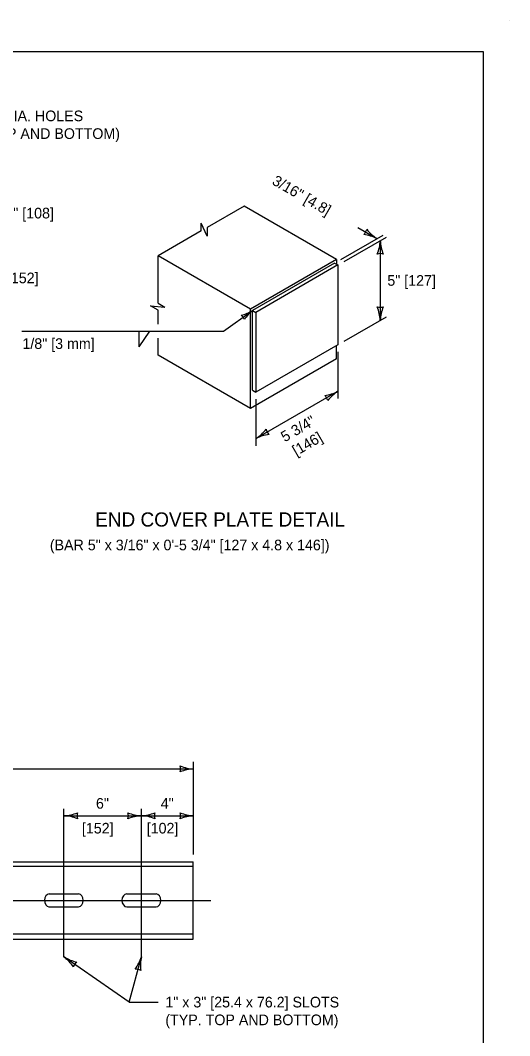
# Model space of a CAD drawing. Extents: x 49991.4 to 50021, y 49987.6 to 50011.4.
# Drawn here: x 50014.14 to 50016.9, y 49993.45 to 49999.18 of the extents above; entities that cross this region are included whole.
import ezdxf

# ---------------------------------------------------------------- set-up
doc = ezdxf.new("R2010")
doc.units = 0
for name, color, linetype in [('Level 1', 7, 'Continuous'), ('Level 2', 7, 'Continuous'), ('Level 3', 7, 'Continuous'), ('Level 4', 7, 'Continuous'), ('Level 5', 7, 'Continuous'), ('Level 6', 7, 'Continuous')]:
    doc.layers.add(name, color=color, linetype=linetype)

msp = doc.modelspace()

# ---------------------------------------------------------------- linework, layer by layer
at = {"layer": 'Level 1'}
for p, q in [((50016.9001, 49999.1756), (50016.9001, 49999.1756)), ((50015.9241, 49997.8254), (50015.4021, 49998.1268)), ((50015.4389, 49997.5453), (50014.9169, 49997.8467)), ((50015.9241, 49997.8254), (50015.4389, 49997.5453)), ((50015.9128, 49997.8059), (50015.4502, 49997.5388)), ((50015.9315, 49997.7951), (50015.4689, 49997.528)), ((50015.9128, 49997.8059), (50015.9315, 49997.7951)), ((50015.9241, 49997.8254), (50015.9241, 49997.7994)), ((50015.9315, 49997.7951), (50015.9315, 49997.3451)), ((50015.4389, 49996.9851), (50015.4389, 49997.5453)), ((50015.4502, 49997.0888), (50015.4502, 49997.5388)), ((50015.4502, 49997.5388), (50015.4689, 49997.528)), ((50015.4689, 49997.528), (50015.4689, 49997.078)), ((50015.9315, 49997.3451), (50015.4689, 49997.078)), ((50015.9241, 49997.2652), (50015.9241, 49997.3408)), ((50015.4389, 49996.9851), (50014.9169, 49997.2865)), ((50015.9241, 49997.2652), (50015.4389, 49996.9851)), ((50015.4502, 49997.0888), (50015.4689, 49997.078)), ((50012.4943, 49994.4284), (50015.1145, 49994.4284)), ((50015.1145, 49993.9918), (50015.1145, 49994.4284)), ((50014.3039, 49994.2465), (50014.4689, 49994.2465)), ((50014.7406, 49994.2465), (50014.9055, 49994.2465)), ((50014.3019, 49994.1739), (50014.4692, 49994.1739)), ((50014.7406, 49994.1738), (50014.9055, 49994.1738)), ((50012.4943, 49993.9918), (50015.1145, 49993.9918))]:
    msp.add_line(p, q, dxfattribs=at)
msp.add_lwpolyline([(49999.3835, 49998.9992), (50016.7501, 49998.9992), (50016.7501, 49987.7988), (49999.3835, 49987.7988)], close=True, dxfattribs=at)
for centre, start_param, end_param in [((50014.3039, 49994.2101), 3.141593, 6.209011), ((50014.4677, 49994.2102), 0.057626, 3.094927), ((50014.7406, 49994.2101), 3.141593, 6.283185), ((50014.9051, 49994.2101), 0.015223, 3.126363)]:
    msp.add_ellipse(centre, major_axis=(0, -0.0364), ratio=0.751168, start_param=start_param, end_param=end_param, dxfattribs=at)
at = {"layer": 'Level 3'}
for p, q in [((50016.043, 49998.0063), (50016.1514, 49997.9437)), ((50015.9475, 49997.8259), (50016.1861, 49997.9637)), ((50015.9662, 49997.8151), (50016.2048, 49997.9529)), ((50016.1701, 49997.9329), (50016.1701, 49997.4829)), ((50015.2858, 49997.4216), (50015.4502, 49997.5388)), ((50015.9662, 49997.3651), (50016.2048, 49997.5029)), ((50014.1494, 49997.4216), (50015.2858, 49997.4216)), ((50014.8096, 49997.4216), (50014.8096, 49997.3325)), ((50014.8694, 49997.4216), (50014.8096, 49997.3325)), ((50015.9315, 49997.3051), (50015.9315, 49997.0426)), ((50015.4689, 49996.8155), (50015.9315, 49997.0826)), ((50015.4689, 49997.038), (50015.4689, 49996.7755)), ((50015.1173, 49994.4684), (50015.1173, 49994.9918)), ((50012.4943, 49994.9518), (50015.1173, 49994.9518)), ((50014.3865, 49994.6877), (50014.8232, 49994.6877)), ((50014.8232, 49994.6877), (50015.1173, 49994.6877)), ((50014.754, 49993.6363), (50014.3865, 49993.8918)), ((50014.754, 49993.6363), (50014.8232, 49993.8918)), ((50014.754, 49993.6363), (50014.9182, 49993.6363))]:
    msp.add_line(p, q, dxfattribs=at)
for centre, radius, start, end in [((50016.0404, 49998.0078), 0.0548, 312.1389, 347.8612), ((50016.045, 49997.7364), 0.233, 62.8274, 82.0772), ((50016.2704, 49998.1315), 0.2223, 217.4561, 237.6396), ((50015.948, 49997.942), 0.2223, 337.456, 357.6395), ((50016.4028, 49997.9444), 0.233, 182.8273, 202.0772), ((50016.1701, 49997.8047), 0.0548, 72.1388, 107.8612), ((50016.1701, 49997.6111), 0.0548, 252.1388, 287.8612), ((50015.9374, 49997.4714), 0.233, 2.8273, 22.0772), ((50016.3923, 49997.4737), 0.2223, 157.456, 177.6395), ((50015.3422, 49997.7043), 0.1976, 282.9456, 303.1291), ((50015.3574, 49997.4727), 0.0487, 17.6284, 53.3508), ((50015.5786, 49997.3763), 0.2071, 128.3169, 147.5668), ((50015.8284, 49997.2796), 0.2223, 277.456, 297.6395), ((50015.8205, 49997.0185), 0.0548, 12.1388, 47.8612), ((50016.0579, 49996.8869), 0.233, 122.8273, 142.0772), ((50015.3426, 49997.0113), 0.233, 302.8273, 322.0772), ((50015.5799, 49996.8796), 0.0548, 192.1388, 227.8612), ((50015.572, 49996.6186), 0.2223, 97.456, 117.6395), ((50015.1265, 49995.1739), 0.2223, 247.456, 267.6395), ((50014.9891, 49994.9518), 0.0548, 342.1388, 17.8612), ((50015.1288, 49994.7191), 0.233, 92.8273, 112.0772), ((50014.3751, 49994.9204), 0.233, 272.8273, 292.0772), ((50014.3774, 49994.4656), 0.2223, 67.456, 87.6395), ((50014.5148, 49994.6877), 0.0548, 162.1388, 197.8612), ((50014.8324, 49994.9098), 0.2223, 247.456, 267.6395), ((50014.695, 49994.6877), 0.0548, 342.1388, 17.8612), ((50014.8347, 49994.455), 0.233, 92.8273, 112.0772), ((50014.8118, 49994.9204), 0.233, 272.8273, 292.0772), ((50014.8141, 49994.4656), 0.2223, 67.456, 87.6395), ((50014.9515, 49994.6877), 0.0548, 162.1388, 197.8612), ((50015.1265, 49994.9098), 0.2223, 247.456, 267.6395), ((50014.9891, 49994.6877), 0.0548, 342.1388, 17.8612), ((50015.1288, 49994.455), 0.233, 92.8273, 112.0772), ((50014.2522, 49993.7147), 0.2223, 32.6387, 52.8222), ((50014.51, 49994.0894), 0.233, 238.01, 257.2599), ((50014.6112, 49993.9587), 0.2223, 322.2925, 342.476), ((50015.0509, 49993.842), 0.233, 167.6638, 186.9136), ((50014.4918, 49993.8186), 0.0548, 127.3215, 163.0439), ((50014.7897, 49993.7681), 0.0548, 56.9753, 92.6976)]:
    msp.add_arc(centre, radius, start, end, dxfattribs=at)
at = {"layer": 'Level 4'}
for p, q in [((50015.1145, 49994.4012), (50012.4943, 49994.4012)), ((50015.1145, 49994.0196), (50012.4943, 49994.0196))]:
    msp.add_line(p, q, dxfattribs=at)
at = {"layer": 'Level 5'}
for p, q in [((50014.3865, 49993.8918), (50014.3865, 49994.7277)), ((50014.8232, 49993.8918), (50014.8232, 49994.7277)), ((50012.3943, 49994.2102), (50015.2145, 49994.2102))]:
    msp.add_line(p, q, dxfattribs=at)
at = {"layer": 'Level 6'}
for p, q in [((50015.4021, 49998.1268), (50015.1941, 49998.0067)), ((50015.1595, 49997.9869), (50015.1595, 49998.0314)), ((50015.1941, 49997.9581), (50015.1595, 49998.0314)), ((50015.1941, 49998.0067), (50015.1941, 49997.9581)), ((50015.1595, 49997.9869), (50014.9169, 49997.8467)), ((50014.9169, 49997.5794), (50014.9169, 49997.8467)), ((50014.8747, 49997.5638), (50014.9555, 49997.5571)), ((50014.9169, 49997.5394), (50014.8747, 49997.5638)), ((50014.9169, 49997.5794), (50014.9555, 49997.5571)), ((50014.9169, 49997.4616), (50014.9169, 49997.5394)), ((50014.9169, 49997.2865), (50014.9169, 49997.3816))]:
    msp.add_line(p, q, dxfattribs=at)

# ---------------------------------------------------------------- texts
at = {"layer": 'Level 2'}
for s, height, p in [('1" [25.4] DIA. HOLES ', 0.06, (50013.7261, 49998.6064)), ('(TYP. TOP AND BOTTOM)', 0.06, (50013.7261, 49998.5064)), ('4 1/4" [108]', 0.06, (50013.9221, 49998.0578)), ('6" [152]', 0.06, (50013.9694, 49997.6922)), ('5" [127]', 0.06, (50016.2101, 49997.6779)), ('1/8" [3 mm] ', 0.06, (50014.1522, 49997.3216)), ('END COVER PLATE DETAIL', 0.08, (50014.5625, 49996.3193)), ('(BAR 5" x 3/16" x 0\'-5 3/4" [127 x 4.8 x 146])', 0.06, (50014.3069, 49996.1855)), ('6"', 0.06, (50014.5669, 49994.7277)), ('4"', 0.06, (50014.9323, 49994.7277)), ('[152]', 0.06, (50014.4878, 49994.5877)), ('[102]', 0.06, (50014.8532, 49994.5877)), ('1" x 3" [25.4 x 76.2] SLOTS', 0.06, (50014.9582, 49993.6063)), ('(TYP. TOP AND BOTTOM)', 0.06, (50014.9582, 49993.5063))]:
    msp.add_text(s, height=height, dxfattribs=at).set_placement(p)
for s, rotation, p in [(' 3/16" [4.8]', 330, (50015.5359, 49998.2644)), ('5 3/4"', 30, (50015.6315, 49996.794)), ('[146]', 30, (50015.6961, 49996.7158))]:
    msp.add_text(s, height=0.06, rotation=rotation, dxfattribs=at).set_placement(p)

doc.saveas('drawing.dxf')
